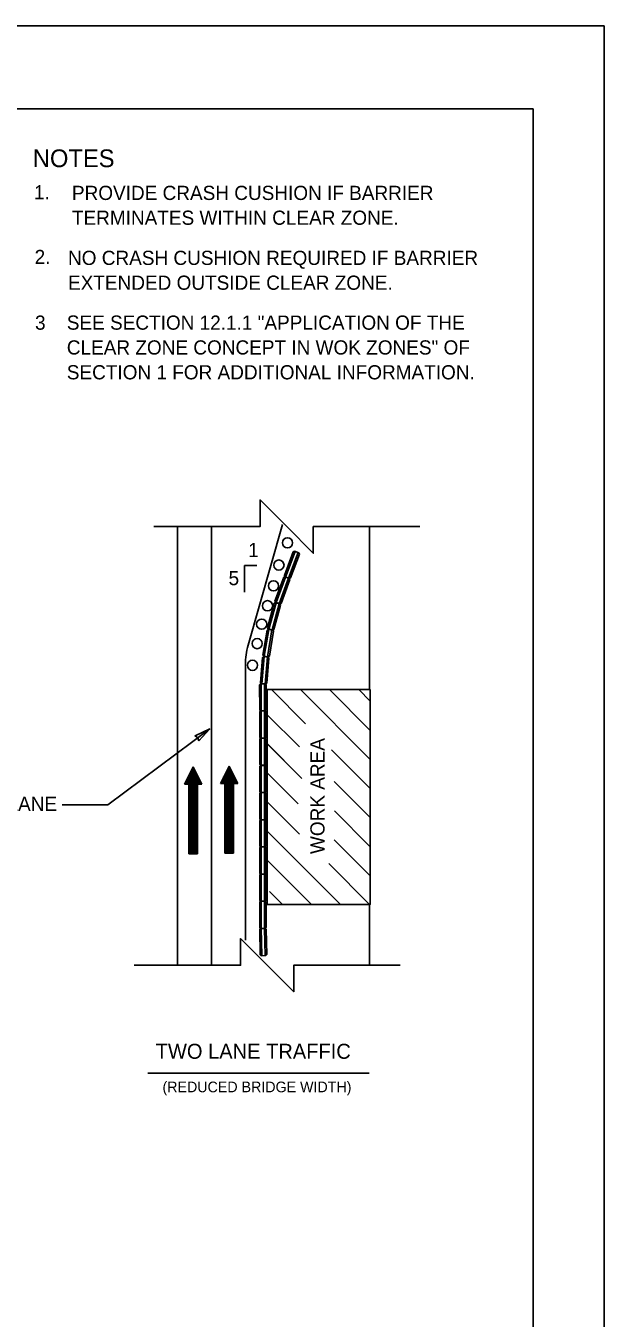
# Model space of a CAD drawing. Extents: x 3033 to 3249, y -403 to -124.
# Drawn here: x 3167.7 to 3249.2, y -305.8 to -123.6 of the extents above; entities that cross this region are included whole.
import ezdxf

# ---------------------------------------------------------------- set-up
doc = ezdxf.new("R2010")
doc.units = 0
for name, color, linetype in [('Level 10', 7, 'Continuous'), ('Level 17', 7, 'Continuous'), ('Level 20', 7, 'Continuous'), ('Level 22', 7, 'Continuous'), ('Level 4', 7, 'Continuous'), ('Level 44', 7, 'Continuous'), ('Level 5', 7, 'Continuous'), ('Level 60', 7, 'Continuous')]:
    doc.layers.add(name, color=color, linetype=linetype)

# ---------------------------------------------------------------- blocks, each defined once
blk = doc.blocks.new('arrow')
at = {"layer": 'Level 60'}
blk.add_lwpolyline([(0.6, 0.12), (0, 0), (0.6, -0.12), (0.56, 0)], close=True, dxfattribs=at)
blk = doc.blocks.new('BREAK')
at = {"layer": 'Level 20'}
blk.add_lwpolyline([(-12.499, 0), (-2.5, 0), (-2.5, 2.5), (0, 0), (2.501, -2.501), (2.501, 0), (12.501, 0)], dxfattribs=at)

msp = doc.modelspace()

# ---------------------------------------------------------------- linework, layer by layer
at = {"layer": 'Level 10'}
for p, q in [((3189.05, -255.9), (3189.05, -194.17)), ((3193.85, -255.9), (3193.85, -194.17)), ((3203.89, -193.89), (3199.04, -210.92)), ((3216.14, -194.26), (3216.14, -217.18)), ((3198.67, -252.51), (3198.65, -213.67)), ((3216.13, -217.18), (3201.72, -217.18)), ((3201.72, -247.47), (3201.72, -217.18)), ((3207.13, -222), (3202.3, -217.18)), ((3216.25, -227.02), (3206.41, -217.18)), ((3216.25, -222.92), (3210.51, -217.18)), ((3216.25, -218.81), (3214.62, -217.18)), ((3216.25, -247.47), (3216.25, -217.18)), ((3206.26, -225.24), (3201.72, -220.71)), ((3206.62, -229.71), (3201.72, -224.81)), ((3204.09, -227.17), (3201.74, -224.82)), ((3216.25, -231.13), (3210.8, -225.67)), ((3191.29, -228.07), (3190.06, -230.53)), ((3190.67, -229.3), (3190.67, -240.34)), ((3190.83, -228.99), (3190.83, -240.34)), ((3190.98, -228.69), (3190.98, -240.34)), ((3191.14, -228.38), (3191.14, -240.34)), ((3191.29, -228.07), (3191.29, -240.34)), ((3191.29, -228.07), (3192.51, -230.53)), ((3191.44, -228.38), (3191.44, -240.34)), ((3191.59, -228.69), (3191.59, -240.34)), ((3191.75, -228.99), (3191.75, -240.34)), ((3191.9, -229.3), (3191.9, -240.34)), ((3196.35, -227.96), (3195.12, -230.41)), ((3195.58, -229.49), (3195.58, -230.41)), ((3195.74, -229.18), (3195.74, -240.23)), ((3195.89, -228.88), (3195.89, -240.23)), ((3196.04, -228.57), (3196.04, -240.23)), ((3196.2, -228.26), (3196.2, -240.23)), ((3196.35, -227.96), (3196.35, -240.23)), ((3196.35, -227.96), (3197.58, -230.41)), ((3196.5, -228.26), (3196.5, -240.23)), ((3196.66, -228.57), (3196.66, -240.23)), ((3196.81, -228.88), (3196.81, -240.23)), ((3196.96, -229.18), (3196.96, -240.23)), ((3197.12, -229.49), (3197.12, -230.41)), ((3206.07, -233.26), (3201.72, -228.91)), ((3190.06, -230.53), (3190.67, -230.53)), ((3190.21, -230.22), (3190.21, -230.53)), ((3190.37, -229.91), (3190.37, -230.53)), ((3190.52, -229.61), (3190.52, -230.53)), ((3190.67, -230.53), (3190.67, -240.34)), ((3191.9, -230.53), (3191.9, -240.34)), ((3191.9, -230.53), (3192.51, -230.53)), ((3192.05, -229.61), (3192.05, -230.53)), ((3192.21, -229.91), (3192.21, -230.53)), ((3192.36, -230.22), (3192.36, -230.53)), ((3195.12, -230.41), (3195.74, -230.41)), ((3195.28, -230.1), (3195.28, -230.41)), ((3195.43, -229.8), (3195.43, -230.41)), ((3195.74, -230.41), (3195.74, -240.23)), ((3196.96, -230.41), (3196.96, -240.23)), ((3196.96, -230.41), (3197.58, -230.41)), ((3197.27, -229.8), (3197.27, -230.41)), ((3197.42, -230.1), (3197.42, -230.41)), ((3216.25, -235.23), (3211.16, -230.14)), ((3206.26, -237.55), (3201.72, -233.02)), ((3216.25, -239.34), (3211.2, -234.29)), ((3212.07, -247.47), (3201.72, -237.13)), ((3216.25, -243.44), (3211.18, -238.37)), ((3190.67, -240.34), (3191.9, -240.34)), ((3195.74, -240.23), (3196.96, -240.23)), ((3207.96, -247.47), (3201.72, -241.23)), ((3216.25, -247.55), (3210.42, -241.71)), ((3203.86, -247.47), (3202.03, -245.65)), ((3216.25, -247.47), (3201.72, -247.47)), ((3216.14, -256.03), (3216.14, -247.47))]:
    msp.add_line(p, q, dxfattribs=at)
for centre in [(3204.58, -196.49), (3203.37, -199.61), (3202.61, -202.55), (3201.77, -205.35), (3200.94, -207.95), (3200.31, -210.69), (3199.64, -213.75)]:
    msp.add_circle(centre, 0.718, dxfattribs=at)
msp.add_arc((3208.65, -213.66), 10, 164.0903, 180.023, dxfattribs=at)
at = {"layer": 'Level 17'}
for p, q in [((3249.22, -123.59), (3033.21, -123.59)), ((3249.22, -402.59), (3249.22, -123.59))]:
    msp.add_line(p, q, dxfattribs=at)
at = {"layer": 'Level 22'}
for p, q in [((3051.75, -135.28), (3239.21, -135.28)), ((3239.21, -135.28), (3239.21, -391.78))]:
    msp.add_line(p, q, dxfattribs=at)
at = {"layer": 'Level 4'}
for p, q in [((3205.38, -197.75), (3204.14, -201.1)), ((3204.31, -201.3), (3205.64, -197.7)), ((3204.74, -201.46), (3206.07, -197.86)), ((3205.01, -201.42), (3206.25, -198.07)), ((3205.55, -197.67), (3205.38, -197.75)), ((3206.17, -197.9), (3205.55, -197.67)), ((3206.25, -198.07), (3206.17, -197.9)), ((3204.05, -201.34), (3202.81, -204.7)), ((3202.98, -204.9), (3204.31, -201.3)), ((3203.41, -205.06), (3204.74, -201.46)), ((3203.68, -205.02), (3204.92, -201.66)), ((3204.22, -201.27), (3204.05, -201.34)), ((3204.14, -201.1), (3204.22, -201.27)), ((3204.84, -201.49), (3204.22, -201.27)), ((3204.22, -201.27), (3204.84, -201.49)), ((3205.01, -201.42), (3204.84, -201.49)), ((3204.92, -201.66), (3204.84, -201.49)), ((3202.71, -205.01), (3201.77, -208.46)), ((3201.96, -208.65), (3202.97, -204.95)), ((3202.4, -208.77), (3203.41, -205.06)), ((3202.66, -208.7), (3203.6, -205.25)), ((3202.87, -204.92), (3202.71, -205.01)), ((3202.81, -204.7), (3202.89, -204.86)), ((3203.51, -205.09), (3202.87, -204.92)), ((3202.89, -204.86), (3203.51, -205.09)), ((3203.68, -205.02), (3203.51, -205.09)), ((3203.6, -205.25), (3203.51, -205.09)), ((3201.69, -208.79), (3201.11, -212.32)), ((3201.31, -212.48), (3201.94, -208.7)), ((3201.84, -208.68), (3201.69, -208.79)), ((3201.77, -208.46), (3201.86, -208.62)), ((3201.77, -212.56), (3202.39, -208.77)), ((3202.49, -208.79), (3201.84, -208.68)), ((3201.86, -208.62), (3202.5, -208.79)), ((3202.02, -212.47), (3202.6, -208.94)), ((3202.6, -208.94), (3202.49, -208.79)), ((3202.66, -208.7), (3202.5, -208.79)), ((3201.05, -212.64), (3200.76, -216.2)), ((3200.98, -216.35), (3201.29, -212.53)), ((3201.2, -212.52), (3201.05, -212.64)), ((3201.11, -212.32), (3201.22, -212.47)), ((3201.86, -212.58), (3201.2, -212.52)), ((3201.22, -212.47), (3201.87, -212.57)), ((3201.44, -216.39), (3201.75, -212.57)), ((3201.68, -216.28), (3201.97, -212.72)), ((3201.97, -212.72), (3201.86, -212.58)), ((3202.02, -212.47), (3201.87, -212.57)), ((3200.78, -216.34), (3200.65, -216.48)), ((3200.65, -216.48), (3200.66, -220.05)), ((3200.76, -216.2), (3200.88, -216.35)), ((3201.45, -216.35), (3200.78, -216.34)), ((3200.89, -220.18), (3200.88, -216.35)), ((3200.88, -216.35), (3201.54, -216.4)), ((3201.35, -220.18), (3201.34, -216.34)), ((3201.58, -216.47), (3201.45, -216.35)), ((3201.68, -216.28), (3201.54, -216.4)), ((3201.58, -220.05), (3201.58, -216.47)), ((3200.66, -220.05), (3200.79, -220.18)), ((3200.79, -220.18), (3200.66, -220.31)), ((3200.66, -220.31), (3200.66, -223.89)), ((3201.45, -220.18), (3200.79, -220.18)), ((3200.79, -220.18), (3201.45, -220.18)), ((3200.89, -224.02), (3200.89, -220.18)), ((3201.35, -224.02), (3201.35, -220.18)), ((3201.58, -220.05), (3201.45, -220.18)), ((3201.58, -220.31), (3201.45, -220.18)), ((3201.58, -223.89), (3201.58, -220.31)), ((3200.66, -223.89), (3200.79, -224.02)), ((3200.79, -224.01), (3200.66, -224.14)), ((3201.45, -224.01), (3200.79, -224.01)), ((3200.79, -224.02), (3201.45, -224.02)), ((3200.89, -227.85), (3200.89, -224.01)), ((3201.35, -227.85), (3201.35, -224.01)), ((3201.58, -223.89), (3201.45, -224.02)), ((3201.58, -224.14), (3201.45, -224.01)), ((3200.66, -224.14), (3200.66, -227.72)), ((3201.58, -227.72), (3201.58, -224.14)), ((3200.66, -227.72), (3200.79, -227.85)), ((3201.58, -227.72), (3201.45, -227.85)), ((3200.66, -227.99), (3200.79, -227.86)), ((3200.66, -231.56), (3200.66, -227.99)), ((3200.79, -227.85), (3201.45, -227.85)), ((3200.79, -227.86), (3201.45, -227.86)), ((3200.89, -227.86), (3200.88, -231.69)), ((3201.35, -227.85), (3201.35, -231.69)), ((3201.58, -227.98), (3201.45, -227.86)), ((3201.58, -227.98), (3201.58, -231.56)), ((3200.79, -231.69), (3200.66, -231.56)), ((3200.66, -231.82), (3200.79, -231.69)), ((3200.66, -235.39), (3200.66, -231.82)), ((3201.45, -231.69), (3200.79, -231.69)), ((3200.79, -231.69), (3201.45, -231.69)), ((3200.89, -231.69), (3200.88, -235.52)), ((3201.35, -231.68), (3201.35, -235.52)), ((3201.58, -231.56), (3201.45, -231.69)), ((3201.58, -231.82), (3201.45, -231.69)), ((3201.58, -231.82), (3201.58, -235.39)), ((3200.79, -235.52), (3200.66, -235.39)), ((3200.66, -235.65), (3200.79, -235.52)), ((3200.66, -239.22), (3200.66, -235.65)), ((3201.45, -235.52), (3200.79, -235.52)), ((3200.79, -235.52), (3201.45, -235.52)), ((3200.89, -235.52), (3200.88, -239.35)), ((3201.35, -235.51), (3201.35, -239.35)), ((3201.58, -235.39), (3201.45, -235.52)), ((3201.58, -235.65), (3201.45, -235.52)), ((3201.58, -235.65), (3201.58, -239.22)), ((3200.79, -239.35), (3200.66, -239.22)), ((3200.66, -239.48), (3200.79, -239.35)), ((3200.66, -243.05), (3200.66, -239.48)), ((3201.45, -239.35), (3200.79, -239.35)), ((3200.79, -239.35), (3201.45, -239.35)), ((3200.89, -239.35), (3200.88, -243.18)), ((3201.35, -239.34), (3201.35, -243.18)), ((3201.58, -239.22), (3201.45, -239.35)), ((3201.58, -239.48), (3201.45, -239.35)), ((3201.58, -239.48), (3201.58, -243.05)), ((3200.79, -243.18), (3200.66, -243.05)), ((3200.66, -243.31), (3200.79, -243.18)), ((3200.66, -246.88), (3200.66, -243.31)), ((3201.45, -243.18), (3200.79, -243.18)), ((3200.79, -243.18), (3201.45, -243.18)), ((3200.89, -243.18), (3200.88, -247.01)), ((3201.35, -243.17), (3201.35, -247.01)), ((3201.58, -243.05), (3201.45, -243.18)), ((3201.58, -243.31), (3201.45, -243.18)), ((3201.58, -243.31), (3201.58, -246.88)), ((3200.79, -247.01), (3200.66, -246.88)), ((3200.66, -247.14), (3200.79, -247.01)), ((3200.66, -250.71), (3200.66, -247.14)), ((3201.45, -247.01), (3200.79, -247.01)), ((3200.79, -247.01), (3201.45, -247.01)), ((3200.89, -247.01), (3200.88, -250.84)), ((3201.35, -247), (3201.35, -250.84)), ((3201.58, -246.88), (3201.45, -247.01)), ((3201.58, -247.14), (3201.45, -247.01)), ((3201.58, -247.14), (3201.58, -250.71)), ((3200.79, -250.84), (3200.66, -250.71)), ((3200.66, -250.98), (3200.79, -250.85)), ((3200.72, -254.56), (3200.66, -250.98)), ((3201.45, -250.84), (3200.79, -250.84)), ((3200.79, -250.85), (3201.45, -250.84)), ((3200.89, -250.85), (3200.95, -254.68)), ((3201.35, -250.84), (3201.41, -254.68)), ((3201.58, -250.71), (3201.45, -250.84)), ((3201.59, -250.97), (3201.45, -250.84)), ((3201.59, -250.97), (3201.65, -254.54)), ((3200.86, -254.69), (3200.72, -254.56)), ((3201.52, -254.67), (3200.86, -254.69)), ((3201.65, -254.54), (3201.52, -254.67))]:
    msp.add_line(p, q, dxfattribs=at)
at = {"layer": 'Level 44'}
msp.add_line((3184.88, -271.26), (3216.07, -271.26), dxfattribs=at)
at = {"layer": 'Level 5'}
for p, q in [((3198.53, -203.45), (3198.53, -199.69)), ((3198.53, -199.69), (3200.24, -199.69))]:
    msp.add_line(p, q, dxfattribs=at)
msp.add_lwpolyline([(3172.81, -233.42), (3179.24, -233.42), (3193.62, -222.71)], dxfattribs=at)

# ---------------------------------------------------------------- block references
for name, p, xscale, yscale, rotation in [('BREAK', (3204.47, -194.19), 1.5, 1.5, 180), ('arrow', (3193.62, -222.71), 3.750000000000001, 3.75, -143.2912714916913), ('BREAK', (3201.71, -256.03), 1.5, 1.5, 180)]:
    msp.add_blockref(name, p, dxfattribs=dict(at, xscale=xscale, yscale=yscale, rotation=rotation))

# ---------------------------------------------------------------- texts
at = {"layer": 'Level 10'}
msp.add_text('WORK AREA', height=2, rotation=90, dxfattribs=at).set_placement((3209.8, -240.36))
at = {"layer": 'Level 44'}
for s, height, p in [('TWO LANE TRAFFIC', 2.1152, (3186, -269.23)), ('(REDUCED BRIDGE WIDTH)', 1.5, (3186.96, -273.95))]:
    msp.add_text(s, height=height, dxfattribs=at).set_placement(p)
at = {"layer": 'Level 5'}
for s, height, p in [('NOTES', 2.5, (3168.68, -143.51)), ('1.', 2, (3168.85, -148.05)), ('PROVIDE CRASH CUSHION IF BARRIER', 2, (3174.19, -148.14)), ('TERMINATES WITHIN CLEAR ZONE.', 2, (3174.19, -151.64)), ('2.', 2, (3168.93, -157.17)), ('NO CRASH CUSHION REQUIRED IF BARRIER', 2, (3173.64, -157.3)), ('EXTENDED OUTSIDE CLEAR ZONE.', 2, (3173.64, -160.8)), ('3', 2, (3168.99, -166.43)), ('SEE SECTION 12.1.1 "APPLICATION OF THE', 2, (3173.47, -166.43)), ('CLEAR ZONE CONCEPT IN WOK ZONES" OF', 2, (3173.47, -169.93)), ('SECTION 1 FOR ADDITIONAL INFORMATION.', 2, (3173.47, -173.43)), ('TEMPORARY LANE', 2, (3147.43, -234.29))]:
    msp.add_text(s, height=height, dxfattribs=at).set_placement(p)
for s, p in [('1', (3199.04, -198.49)), ('5', (3196.27, -202.45))]:
    msp.add_text(s, height=2, rotation=360, dxfattribs=at).set_placement(p)

doc.saveas('drawing.dxf')
